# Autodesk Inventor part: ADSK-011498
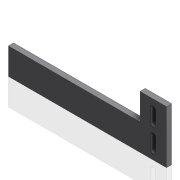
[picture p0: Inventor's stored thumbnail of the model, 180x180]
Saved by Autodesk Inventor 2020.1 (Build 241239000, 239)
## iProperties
Created: 2000-02
Part Number: ADSK-011498
Material: RA HRS
Document SubType Name: Modeling
Designer: sspink
Density: 7.83 g/cm^3
Appearance: Métal - Acier
Mass: 1375.85 g
Surface Area: 448.646 cm^2
Volume: 175.716 cm^3
Control State: 0
Checked Out: False
Master: False
Shininess: 0.0
Length Units: 11269
Angle Units: 11279
Time Units: 11290
Mass Units: 11283
Length Display Precision: 3
Angle Display Precision: 2
Compacted: True
Cutlength: 12.19
Material Desc: FLAT,HRS,0.375 X 4.00
Material_number: A084411
Dimensions: 305x102x10 mm
Mass: 1,376 kg
DocNumber: ADSK-011498.ipt
Folder: 01 - Themengebiete\Simplification\01 - Packaging machine\
VDS_Category: 3D Komponenten
Density: 0.0
Volumn: 0.0
Area: 0.0
PropertySet Name: Model Information
Author: sspink
Revision Number: -
Title: plate
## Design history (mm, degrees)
node "Solide1"
  node "Extrusion1" dims "d2" = 10, "d3" = 0
  node "Extrusion2" dims "d5" = 51, "d6" = 0
  node "Extrusion3" dims "d13" = 50.8, "d14" = 0
sketch "Sketch1"
  geometry: L1 (0, 0)-(305, 0); L2 (305, 0)-(305, 51); L3 (305, 51)-(0, 51); L4 (0, 51)-(0, 0)
  constraints: 8 end point, 2 parallel, 1 horizontal, 1 perpendicular
  dimensions: "d0" = 51 distance between parallel lines of L1 L3; "d1" = 305 distance between parallel lines of L2 L4
sketch "Sketch2"
  geometry: L1 (0, -10)-(305, -10) reference; L2 (305, 0)-(305, -10) reference; L3 (305, 0)-(0, 0) reference; L4 (254, 0)-(254, -10)
  constraints: 2 end point, 2 point on line, 1 perpendicular
  dimensions: "d4" = 51 distance between parallel lines of L2 L4
sketch "Sketch3"
  geometry: L1 (-254, 102)-(-305, 102) reference; L2 (-284, 86)-(-275, 86); L3 (-275, 86)-(-275, 60.6); L4 (-275, 60.6)-(-284, 60.6); L5 (-284, 60.6)-(-284, 86); L6 (-284, 41)-(-275, 41); L7 (-275, 41)-(-275, 15.6); L8 (-275, 15.6)-(-284, 15.6); L9 (-284, 15.6)-(-284, 41); A1 r 4.5 centre (-279.5, 86) between (-275, 86) and (-284, 86); A2 r 4.5 centre (-279.5, 41) between (-275, 41) and (-284, 41); A3 r 4.5 centre (-279.5, 60.6) between (-284, 60.6) and (-275, 60.6); A4 r 4.5 centre (-279.5, 15.6) between (-284, 15.6) and (-275, 15.6); 2 further points
  constraints: 16 end point, 8 point on circle, 4 centre point, 4 parallel, 4 tangent, 2 equal length, 2 horizontal, 2 midpoint, 2 perpendicular, 2 vertical alignment
  dimensions: "d7" = 25.4 distance of L2.end L3.end; "d9" = 9 distance of L2.start L2.end; "d10" = 16 distance from line of A1.centre L1; "d15" = 45 distance between parallel lines of L6 L2
workplane "Arbeitsebene1"
node "Corps solides"
node "Corps surfaciques"
